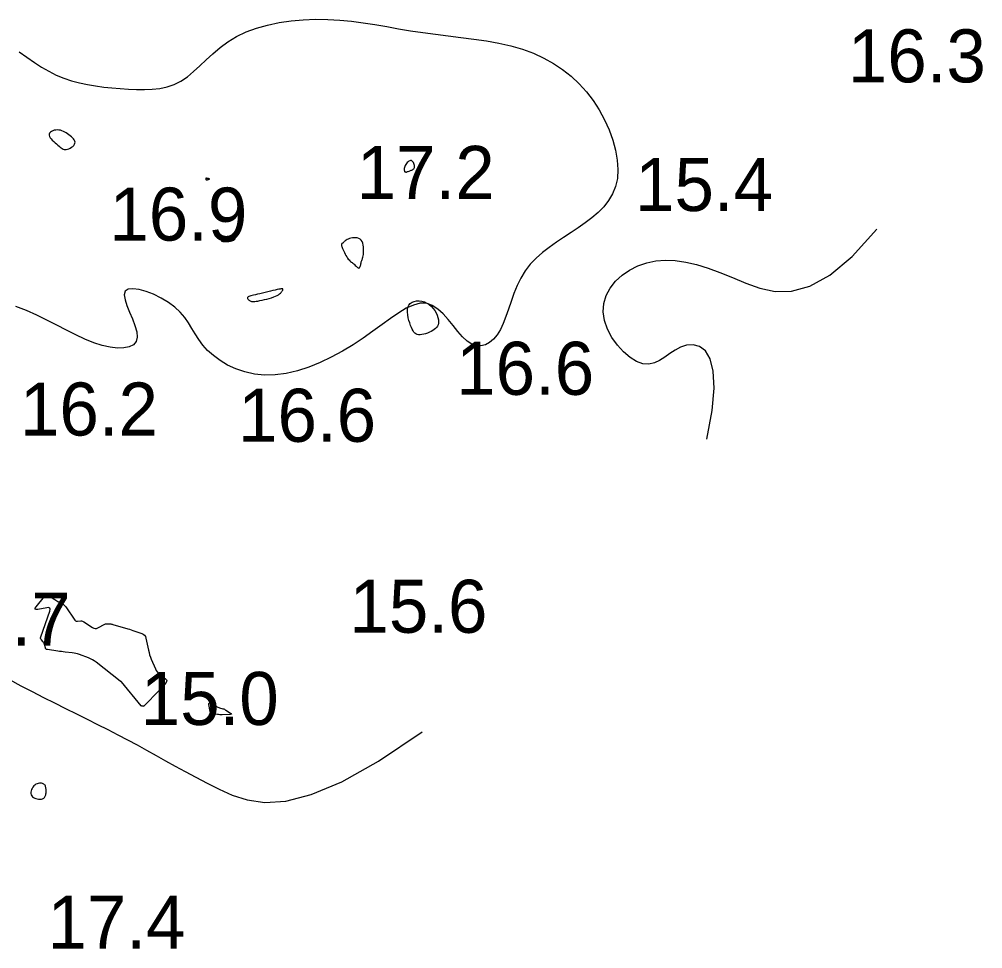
# Model space of a CAD drawing. Extents: x 3040093 to 3056816, y 408076 to 509144.
# Drawn here: x 3045686.7 to 3045777.5, y 433863.6 to 433951.2 of the extents above; entities that cross this region are included whole.
import ezdxf

# ---------------------------------------------------------------- set-up
doc = ezdxf.new("R2010")
doc.units = 0
for name, color, linetype in [('V-CHAN-CONT-EL15', 7, 'Continuous'), ('V-CHAN-CONT-EL17', 7, 'Continuous'), ('V-TOPO-SOUN-0610', 7, 'Continuous')]:
    doc.layers.add(name, color=color, linetype=linetype)

msp = doc.modelspace()

# ---------------------------------------------------------------- linework, layer by layer
at = {"layer": 'V-CHAN-CONT-EL15'}
for points in [[(3045700.137, 433888.23), (3045700.06, 433888.141), (3045699.981, 433888.054), (3045699.9, 433887.97), (3045698.417, 433886.459), (3045698.401, 433886.446), (3045698.384, 433886.438), (3045698.365, 433886.435), (3045698.345, 433886.436), (3045698.225, 433886.457), (3045698.215, 433886.459), (3045698.198, 433886.464), (3045698.192, 433886.466), (3045698.186, 433886.469), (3045698.175, 433886.476), (3045698.17, 433886.479), (3045698.166, 433886.484), (3045696.303, 433888.739), (3045696.295, 433888.748), (3045696.286, 433888.755), (3045696.277, 433888.761), (3045696.266, 433888.765), (3045696.223, 433888.782), (3045696.212, 433888.786), (3045696.202, 433888.792), (3045696.192, 433888.798), (3045696.183, 433888.804), (3045693.903, 433890.589), (3045693.734, 433890.711), (3045693.558, 433890.82), (3045693.374, 433890.916), (3045693.182, 433890.998), (3045692.333, 433891.326), (3045692.171, 433891.383), (3045692.005, 433891.428), (3045691.838, 433891.463), (3045691.667, 433891.486), (3045690.979, 433891.555), (3045690.807, 433891.574), (3045690.635, 433891.594), (3045690.464, 433891.616), (3045690.293, 433891.641), (3045689.315, 433891.786), (3045689.246, 433891.805), (3045689.192, 433891.84), (3045689.152, 433891.89), (3045689.126, 433891.956), (3045689.048, 433892.261), (3045689.027, 433892.329), (3045688.998, 433892.393), (3045688.962, 433892.454), (3045688.92, 433892.51), (3045688.735, 433892.73), (3045688.697, 433892.787), (3045688.677, 433892.847), (3045688.674, 433892.91), (3045688.689, 433892.976), (3045689.533, 433895.411), (3045689.568, 433895.583), (3045689.533, 433895.695), (3045689.428, 433895.746), (3045689.253, 433895.736), (3045688.412, 433895.577), (3045688.245, 433895.563), (3045688.165, 433895.6), (3045688.171, 433895.689), (3045688.264, 433895.828), (3045689.057, 433896.788), (3045689.152, 433896.875), (3045689.255, 433896.915), (3045689.364, 433896.908), (3045689.481, 433896.853), (3045690.032, 433896.496), (3045690.119, 433896.44), (3045690.207, 433896.386), (3045690.296, 433896.334), (3045690.386, 433896.283), (3045690.747, 433896.083), (3045690.833, 433896.028), (3045690.912, 433895.965), (3045690.983, 433895.893), (3045691.045, 433895.813), (3045691.912, 433894.567), (3045691.961, 433894.512), (3045692.018, 433894.475), (3045692.083, 433894.456), (3045692.156, 433894.454), (3045692.466, 433894.485), (3045692.542, 433894.486), (3045692.614, 433894.474), (3045692.683, 433894.45), (3045692.749, 433894.412), (3045693.56, 433893.855), (3045693.682, 433893.791), (3045693.807, 433893.765), (3045693.933, 433893.776), (3045694.062, 433893.826), (3045694.726, 433894.174), (3045694.785, 433894.2), (3045694.846, 433894.218), (3045694.909, 433894.227), (3045694.973, 433894.227), (3045695.235, 433894.211), (3045695.3, 433894.205), (3045695.365, 433894.196), (3045695.429, 433894.183), (3045695.492, 433894.166), (3045696.891, 433893.751), (3045697.058, 433893.7), (3045697.224, 433893.647), (3045697.39, 433893.593), (3045697.555, 433893.536), (3045698.213, 433893.306), (3045698.362, 433893.234), (3045698.478, 433893.134), (3045698.562, 433893.006), (3045698.614, 433892.849), (3045698.849, 433891.717), (3045698.9, 433891.503), (3045698.96, 433891.292), (3045699.031, 433891.085), (3045699.113, 433890.881), (3045699.507, 433889.964), (3045699.579, 433889.822), (3045699.666, 433889.692), (3045699.77, 433889.574), (3045699.889, 433889.468), (3045700.468, 433889.015), (3045700.54, 433888.941), (3045700.57, 433888.861), (3045700.559, 433888.776), (3045700.506, 433888.687), (3045700.212, 433888.321)], [(3045705.943, 433886.185), (3045706.017, 433886.154), (3045706.088, 433886.118), (3045706.157, 433886.077), (3045706.59, 433885.801), (3045706.658, 433885.747), (3045706.675, 433885.708), (3045706.641, 433885.683), (3045706.554, 433885.672), (3045705.798, 433885.647), (3045705.687, 433885.645), (3045705.576, 433885.646), (3045705.465, 433885.652), (3045705.355, 433885.661), (3045704.913, 433885.703), (3045704.814, 433885.726), (3045704.739, 433885.774), (3045704.686, 433885.847), (3045704.656, 433885.944), (3045704.548, 433886.607), (3045704.543, 433886.711), (3045704.572, 433886.766), (3045704.635, 433886.774), (3045704.73, 433886.734), (3045705.263, 433886.43), (3045705.334, 433886.392), (3045705.407, 433886.358), (3045705.482, 433886.329), (3045705.558, 433886.304), (3045705.867, 433886.211)]]:
    msp.add_lwpolyline(points, close=True, dxfattribs=at)
at = {"layer": 'V-CHAN-CONT-EL17'}
for points in [[(3045686.664, 433948.139), (3045687.389, 433947.637), (3045688.089, 433947.16), (3045688.774, 433946.718), (3045689.456, 433946.316), (3045690.149, 433945.965), (3045690.861, 433945.669), (3045691.591, 433945.424), (3045692.337, 433945.224), (3045693.095, 433945.063), (3045693.862, 433944.935), (3045694.634, 433944.833), (3045695.408, 433944.752), (3045696.182, 433944.686), (3045696.951, 433944.629), (3045697.713, 433944.593), (3045698.463, 433944.586), (3045699.198, 433944.621), (3045699.914, 433944.709), (3045700.608, 433944.86), (3045701.275, 433945.086), (3045701.912, 433945.399), (3045702.518, 433945.804), (3045703.107, 433946.285), (3045703.694, 433946.821), (3045704.295, 433947.391), (3045704.925, 433947.975), (3045705.6, 433948.55), (3045706.337, 433949.097), (3045707.151, 433949.594), (3045708.053, 433950.023), (3045709.034, 433950.384), (3045710.078, 433950.677), (3045711.172, 433950.906), (3045712.302, 433951.071), (3045713.452, 433951.176), (3045714.609, 433951.221), (3045715.758, 433951.21), (3045716.889, 433951.144), (3045718.003, 433951.034), (3045719.109, 433950.887), (3045720.212, 433950.715), (3045721.318, 433950.527), (3045722.435, 433950.333), (3045723.569, 433950.142), (3045724.726, 433949.964), (3045725.91, 433949.805), (3045727.114, 433949.658), (3045728.325, 433949.511), (3045729.534, 433949.354), (3045730.729, 433949.174), (3045731.899, 433948.961), (3045733.035, 433948.703), (3045734.123, 433948.39), (3045735.157, 433948.011), (3045736.132, 433947.566), (3045737.051, 433947.056), (3045737.912, 433946.481), (3045738.716, 433945.842), (3045739.462, 433945.14), (3045740.15, 433944.377), (3045740.781, 433943.552), (3045741.353, 433942.669), (3045741.859, 433941.743), (3045742.291, 433940.79), (3045742.642, 433939.828), (3045742.904, 433938.873), (3045743.069, 433937.942), (3045743.129, 433937.052), (3045743.076, 433936.221), (3045742.905, 433935.46), (3045742.627, 433934.767), (3045742.252, 433934.132), (3045741.795, 433933.547), (3045741.267, 433933.006), (3045740.681, 433932.498), (3045740.05, 433932.017), (3045739.386, 433931.554), (3045738.701, 433931.101), (3045738.008, 433930.649), (3045737.319, 433930.191), (3045736.647, 433929.716), (3045736.003, 433929.218), (3045735.401, 433928.687), (3045734.852, 433928.115), (3045734.369, 433927.493), (3045733.959, 433926.818), (3045733.612, 433926.102), (3045733.315, 433925.364), (3045733.051, 433924.621), (3045732.807, 433923.891), (3045732.567, 433923.192), (3045732.318, 433922.542), (3045732.044, 433921.959), (3045731.734, 433921.459), (3045731.391, 433921.049), (3045731.018, 433920.737), (3045730.622, 433920.53), (3045730.208, 433920.433), (3045729.78, 433920.454), (3045729.345, 433920.599), (3045728.906, 433920.875), (3045728.468, 433921.279), (3045728.028, 433921.779), (3045727.581, 433922.333), (3045727.121, 433922.898), (3045726.644, 433923.433), (3045726.146, 433923.896), (3045725.62, 433924.245), (3045725.063, 433924.437), (3045724.471, 433924.444), (3045723.839, 433924.278), (3045723.167, 433923.968), (3045722.451, 433923.538), (3045721.69, 433923.016), (3045720.88, 433922.428), (3045720.021, 433921.799), (3045719.109, 433921.157), (3045718.144, 433920.526), (3045717.136, 433919.922), (3045716.095, 433919.359), (3045715.033, 433918.853), (3045713.961, 433918.417), (3045712.891, 433918.067), (3045711.833, 433917.816), (3045710.8, 433917.679), (3045709.8, 433917.667), (3045708.844, 433917.769), (3045707.938, 433917.971), (3045707.09, 433918.26), (3045706.307, 433918.621), (3045705.598, 433919.04), (3045704.97, 433919.503), (3045704.43, 433919.995), (3045703.981, 433920.505), (3045703.602, 433921.026), (3045703.267, 433921.551), (3045702.949, 433922.077), (3045702.624, 433922.599), (3045702.264, 433923.11), (3045701.844, 433923.606), (3045701.337, 433924.081), (3045700.728, 433924.53), (3045700.047, 433924.936), (3045699.332, 433925.285), (3045698.625, 433925.558), (3045697.964, 433925.74), (3045697.39, 433925.815), (3045696.942, 433925.765), (3045696.66, 433925.575), (3045696.569, 433925.236), (3045696.639, 433924.773), (3045696.821, 433924.22), (3045697.069, 433923.608), (3045697.337, 433922.973), (3045697.579, 433922.345), (3045697.747, 433921.759), (3045697.795, 433921.248), (3045697.687, 433920.839), (3045697.429, 433920.534), (3045697.039, 433920.331), (3045696.534, 433920.226), (3045695.93, 433920.216), (3045695.244, 433920.297), (3045694.493, 433920.468), (3045693.695, 433920.724), (3045692.863, 433921.06), (3045692.002, 433921.459), (3045691.114, 433921.903), (3045690.202, 433922.372), (3045689.266, 433922.848), (3045688.31, 433923.312), (3045687.335, 433923.745), (3045686.343, 433924.127)], [(3045751.498, 433911.616), (3045752.009, 433914.327), (3045752.199, 433916.451), (3045752.122, 433918.051), (3045751.831, 433919.194), (3045751.38, 433919.943), (3045750.823, 433920.363), (3045750.213, 433920.52), (3045749.604, 433920.478), (3045749.039, 433920.297), (3045748.515, 433920.022), (3045748.019, 433919.696), (3045747.538, 433919.359), (3045747.058, 433919.053), (3045746.565, 433918.819), (3045746.048, 433918.698), (3045745.491, 433918.732), (3045744.89, 433918.95), (3045744.266, 433919.335), (3045743.651, 433919.862), (3045743.073, 433920.5), (3045742.564, 433921.224), (3045742.154, 433922.004), (3045741.871, 433922.815), (3045741.747, 433923.626), (3045741.804, 433924.415), (3045742.03, 433925.166), (3045742.405, 433925.868), (3045742.91, 433926.511), (3045743.525, 433927.082), (3045744.231, 433927.571), (3045745.008, 433927.966), (3045745.837, 433928.257), (3045746.701, 433928.434), (3045747.601, 433928.5), (3045748.539, 433928.461), (3045749.52, 433928.322), (3045750.547, 433928.088), (3045751.622, 433927.765), (3045752.75, 433927.359), (3045753.934, 433926.874), (3045755.18, 433926.336), (3045756.51, 433925.856), (3045757.945, 433925.562), (3045759.51, 433925.585), (3045761.228, 433926.053), (3045763.123, 433927.098), (3045765.218, 433928.848), (3045767.536, 433931.434)], [(3045685.728, 433888.957), (3045686.812, 433888.381), (3045687.887, 433887.823), (3045688.95, 433887.28), (3045690.001, 433886.751), (3045691.035, 433886.234), (3045692.053, 433885.727), (3045693.054, 433885.229), (3045694.037, 433884.737), (3045695.002, 433884.249), (3045695.949, 433883.764), (3045696.877, 433883.28), (3045697.785, 433882.794), (3045698.677, 433882.305), (3045699.562, 433881.81), (3045700.454, 433881.309), (3045701.368, 433880.798), (3045702.317, 433880.277), (3045703.315, 433879.742), (3045704.374, 433879.193), (3045705.51, 433878.628), (3045706.747, 433878.064), (3045708.154, 433877.607), (3045709.812, 433877.379), (3045711.8, 433877.506), (3045714.2, 433878.11), (3045717.092, 433879.317), (3045720.556, 433881.251), (3045724.673, 433884.036)]]:
    msp.add_lwpolyline(points, dxfattribs=at)
for points in [[(3045691.217, 433938.96), (3045691.344, 433939.006), (3045691.472, 433939.069), (3045691.595, 433939.146), (3045691.707, 433939.233), (3045691.802, 433939.329), (3045691.874, 433939.43), (3045691.917, 433939.533), (3045691.927, 433939.637), (3045691.906, 433939.741), (3045691.857, 433939.844), (3045691.785, 433939.946), (3045691.695, 433940.046), (3045691.589, 433940.144), (3045691.472, 433940.24), (3045691.349, 433940.333), (3045691.221, 433940.423), (3045691.091, 433940.507), (3045690.958, 433940.585), (3045690.823, 433940.653), (3045690.684, 433940.709), (3045690.543, 433940.752), (3045690.399, 433940.779), (3045690.253, 433940.788), (3045690.105, 433940.778), (3045689.96, 433940.749), (3045689.824, 433940.704), (3045689.702, 433940.644), (3045689.6, 433940.57), (3045689.523, 433940.484), (3045689.478, 433940.388), (3045689.47, 433940.284), (3045689.502, 433940.172), (3045689.569, 433940.056), (3045689.664, 433939.936), (3045689.781, 433939.815), (3045689.911, 433939.695), (3045690.047, 433939.577), (3045690.182, 433939.463), (3045690.31, 433939.356), (3045690.424, 433939.257), (3045690.527, 433939.167), (3045690.621, 433939.089), (3045690.711, 433939.024), (3045690.8, 433938.975), (3045690.892, 433938.942), (3045690.99, 433938.927), (3045691.097, 433938.933)], [(3045723.08, 433936.821), (3045723.125, 433936.814), (3045723.175, 433936.819), (3045723.231, 433936.833), (3045723.292, 433936.854), (3045723.356, 433936.879), (3045723.423, 433936.906), (3045723.493, 433936.933), (3045723.564, 433936.958), (3045723.635, 433936.981), (3045723.703, 433937.007), (3045723.766, 433937.036), (3045723.823, 433937.073), (3045723.87, 433937.118), (3045723.906, 433937.174), (3045723.928, 433937.244), (3045723.936, 433937.329), (3045723.929, 433937.424), (3045723.908, 433937.523), (3045723.876, 433937.622), (3045723.832, 433937.714), (3045723.779, 433937.793), (3045723.717, 433937.853), (3045723.648, 433937.89), (3045723.572, 433937.899), (3045723.493, 433937.881), (3045723.412, 433937.841), (3045723.331, 433937.783), (3045723.254, 433937.709), (3045723.183, 433937.625), (3045723.119, 433937.533), (3045723.066, 433937.437), (3045723.026, 433937.34), (3045722.997, 433937.246), (3045722.98, 433937.156), (3045722.973, 433937.072), (3045722.977, 433936.997), (3045722.99, 433936.932), (3045723.012, 433936.88), (3045723.042, 433936.843)], [(3045704.406, 433936.094), (3045704.442, 433936.102), (3045704.479, 433936.111), (3045704.516, 433936.121), (3045704.548, 433936.132), (3045704.576, 433936.143), (3045704.596, 433936.153), (3045704.607, 433936.162), (3045704.607, 433936.17), (3045704.597, 433936.176), (3045704.579, 433936.182), (3045704.555, 433936.187), (3045704.527, 433936.191), (3045704.496, 433936.194), (3045704.466, 433936.198), (3045704.437, 433936.202), (3045704.411, 433936.206), (3045704.389, 433936.211), (3045704.369, 433936.215), (3045704.352, 433936.219), (3045704.336, 433936.223), (3045704.323, 433936.227), (3045704.312, 433936.23), (3045704.301, 433936.231), (3045704.292, 433936.232), (3045704.283, 433936.231), (3045704.276, 433936.23), (3045704.269, 433936.227), (3045704.263, 433936.223), (3045704.258, 433936.217), (3045704.253, 433936.211), (3045704.25, 433936.203), (3045704.247, 433936.194), (3045704.246, 433936.183), (3045704.245, 433936.172), (3045704.245, 433936.161), (3045704.246, 433936.15), (3045704.248, 433936.138), (3045704.251, 433936.127), (3045704.255, 433936.117), (3045704.26, 433936.108), (3045704.267, 433936.1), (3045704.277, 433936.094), (3045704.289, 433936.089), (3045704.304, 433936.085), (3045704.322, 433936.084), (3045704.346, 433936.085), (3045704.373, 433936.088)], [(3045706.817, 433930.36), (3045706.905, 433930.405), (3045706.971, 433930.454), (3045707.016, 433930.506), (3045707.042, 433930.559), (3045707.048, 433930.609), (3045707.037, 433930.656), (3045707.009, 433930.697), (3045706.964, 433930.729), (3045706.905, 433930.753), (3045706.832, 433930.768), (3045706.747, 433930.775), (3045706.652, 433930.773), (3045706.547, 433930.762), (3045706.435, 433930.742), (3045706.316, 433930.713), (3045706.194, 433930.674), (3045706.072, 433930.629), (3045705.958, 433930.58), (3045705.857, 433930.527), (3045705.777, 433930.474), (3045705.722, 433930.423), (3045705.699, 433930.376), (3045705.714, 433930.336), (3045705.772, 433930.304), (3045705.865, 433930.28), (3045705.986, 433930.265), (3045706.126, 433930.258), (3045706.277, 433930.261), (3045706.429, 433930.272), (3045706.576, 433930.292), (3045706.707, 433930.322)], [(3045718.763, 433927.795), (3045718.795, 433927.844), (3045718.822, 433927.909), (3045718.844, 433927.988), (3045718.864, 433928.075), (3045718.883, 433928.165), (3045718.902, 433928.255), (3045718.922, 433928.339), (3045718.945, 433928.414), (3045718.97, 433928.485), (3045718.997, 433928.554), (3045719.023, 433928.627), (3045719.049, 433928.708), (3045719.074, 433928.801), (3045719.097, 433928.912), (3045719.117, 433929.044), (3045719.132, 433929.2), (3045719.141, 433929.375), (3045719.141, 433929.561), (3045719.129, 433929.75), (3045719.104, 433929.936), (3045719.061, 433930.111), (3045718.999, 433930.267), (3045718.916, 433930.396), (3045718.809, 433930.494), (3045718.683, 433930.561), (3045718.543, 433930.602), (3045718.394, 433930.62), (3045718.241, 433930.618), (3045718.09, 433930.601), (3045717.946, 433930.572), (3045717.814, 433930.534), (3045717.697, 433930.491), (3045717.597, 433930.444), (3045717.51, 433930.395), (3045717.436, 433930.346), (3045717.372, 433930.297), (3045717.319, 433930.251), (3045717.273, 433930.21), (3045717.234, 433930.173), (3045717.2, 433930.144), (3045717.17, 433930.12), (3045717.145, 433930.101), (3045717.124, 433930.086), (3045717.105, 433930.074), (3045717.09, 433930.064), (3045717.077, 433930.054), (3045717.066, 433930.044), (3045717.057, 433930.032), (3045717.05, 433930.016), (3045717.047, 433929.995), (3045717.049, 433929.965), (3045717.056, 433929.924), (3045717.071, 433929.871), (3045717.093, 433929.802), (3045717.124, 433929.716), (3045717.165, 433929.611), (3045717.214, 433929.49), (3045717.271, 433929.36), (3045717.334, 433929.223), (3045717.401, 433929.085), (3045717.473, 433928.95), (3045717.546, 433928.823), (3045717.62, 433928.709), (3045717.694, 433928.61), (3045717.767, 433928.526), (3045717.841, 433928.453), (3045717.914, 433928.388), (3045717.988, 433928.328), (3045718.061, 433928.271), (3045718.135, 433928.212), (3045718.209, 433928.15), (3045718.283, 433928.083), (3045718.357, 433928.012), (3045718.429, 433927.944), (3045718.498, 433927.881), (3045718.563, 433927.828), (3045718.623, 433927.788), (3045718.677, 433927.767), (3045718.724, 433927.769)], [(3045709.367, 433924.688), (3045709.574, 433924.732), (3045709.794, 433924.782), (3045710.019, 433924.84), (3045710.243, 433924.902), (3045710.458, 433924.969), (3045710.658, 433925.038), (3045710.836, 433925.109), (3045710.986, 433925.181), (3045711.109, 433925.252), (3045711.21, 433925.321), (3045711.289, 433925.388), (3045711.352, 433925.452), (3045711.4, 433925.512), (3045711.437, 433925.566), (3045711.466, 433925.614), (3045711.49, 433925.654), (3045711.508, 433925.689), (3045711.522, 433925.717), (3045711.531, 433925.741), (3045711.536, 433925.76), (3045711.536, 433925.775), (3045711.533, 433925.787), (3045711.526, 433925.797), (3045711.514, 433925.805), (3045711.494, 433925.811), (3045711.463, 433925.813), (3045711.416, 433925.81), (3045711.348, 433925.801), (3045711.257, 433925.786), (3045711.138, 433925.762), (3045710.986, 433925.73), (3045710.8, 433925.687), (3045710.585, 433925.637), (3045710.35, 433925.582), (3045710.102, 433925.523), (3045709.849, 433925.462), (3045709.599, 433925.402), (3045709.359, 433925.346), (3045709.138, 433925.294), (3045708.942, 433925.25), (3045708.771, 433925.211), (3045708.625, 433925.177), (3045708.502, 433925.145), (3045708.4, 433925.115), (3045708.32, 433925.085), (3045708.26, 433925.054), (3045708.219, 433925.019), (3045708.196, 433924.981), (3045708.189, 433924.939), (3045708.196, 433924.895), (3045708.216, 433924.851), (3045708.247, 433924.807), (3045708.286, 433924.764), (3045708.333, 433924.725), (3045708.385, 433924.69), (3045708.442, 433924.66), (3045708.505, 433924.637), (3045708.577, 433924.62), (3045708.662, 433924.61), (3045708.761, 433924.608), (3045708.879, 433924.614), (3045709.018, 433924.629), (3045709.18, 433924.654)], [(3045723.491, 433922.583), (3045723.416, 433922.827), (3045723.35, 433923.083), (3045723.301, 433923.342), (3045723.275, 433923.597), (3045723.279, 433923.839), (3045723.32, 433924.061), (3045723.403, 433924.253), (3045723.534, 433924.41), (3045723.706, 433924.531), (3045723.91, 433924.614), (3045724.138, 433924.66), (3045724.381, 433924.668), (3045724.63, 433924.639), (3045724.876, 433924.572), (3045725.112, 433924.467), (3045725.328, 433924.326), (3045725.524, 433924.154), (3045725.697, 433923.958), (3045725.848, 433923.747), (3045725.974, 433923.528), (3045726.074, 433923.307), (3045726.148, 433923.093), (3045726.195, 433922.893), (3045726.213, 433922.713), (3045726.204, 433922.552), (3045726.17, 433922.408), (3045726.111, 433922.279), (3045726.03, 433922.162), (3045725.927, 433922.056), (3045725.805, 433921.959), (3045725.665, 433921.868), (3045725.509, 433921.782), (3045725.341, 433921.702), (3045725.164, 433921.631), (3045724.985, 433921.571), (3045724.807, 433921.523), (3045724.634, 433921.491), (3045724.471, 433921.476), (3045724.323, 433921.48), (3045724.192, 433921.506), (3045724.077, 433921.555), (3045723.976, 433921.626), (3045723.885, 433921.722), (3045723.802, 433921.842), (3045723.723, 433921.988), (3045723.647, 433922.159), (3045723.57, 433922.358)], [(3045688.687, 433877.669), (3045688.775, 433877.682), (3045688.853, 433877.705), (3045688.92, 433877.738), (3045688.979, 433877.78), (3045689.029, 433877.83), (3045689.072, 433877.888), (3045689.107, 433877.953), (3045689.135, 433878.024), (3045689.158, 433878.1), (3045689.175, 433878.181), (3045689.187, 433878.265), (3045689.194, 433878.35), (3045689.197, 433878.437), (3045689.195, 433878.524), (3045689.19, 433878.61), (3045689.182, 433878.694), (3045689.169, 433878.775), (3045689.151, 433878.852), (3045689.125, 433878.924), (3045689.092, 433878.99), (3045689.049, 433879.048), (3045688.995, 433879.099), (3045688.929, 433879.141), (3045688.85, 433879.172), (3045688.761, 433879.193), (3045688.664, 433879.201), (3045688.56, 433879.195), (3045688.454, 433879.175), (3045688.346, 433879.139), (3045688.24, 433879.086), (3045688.139, 433879.014), (3045688.044, 433878.924), (3045687.958, 433878.819), (3045687.884, 433878.703), (3045687.825, 433878.579), (3045687.784, 433878.453), (3045687.763, 433878.327), (3045687.764, 433878.207), (3045687.791, 433878.096), (3045687.844, 433877.998), (3045687.921, 433877.913), (3045688.016, 433877.841), (3045688.124, 433877.781), (3045688.24, 433877.735), (3045688.359, 433877.7), (3045688.477, 433877.678), (3045688.587, 433877.668)]]:
    msp.add_lwpolyline(points, close=True, dxfattribs=at)

# ---------------------------------------------------------------- texts
at = {"layer": 'V-TOPO-SOUN-0610'}
for s, p in [('16.3 ', (3045764.813, 433945.27)), ('17.2 ', (3045718.493, 433934.28)), ('15.4 ', (3045744.743, 433933.14)), ('16.9 ', (3045695.163, 433930.35)), ('16.6 ', (3045727.873, 433915.81)), ('16.2 ', (3045686.733, 433911.97)), ('16.6 ', (3045707.303, 433911.38)), ('15.6 ', (3045717.803, 433893.37)), ('14.7 ', (3045678.503, 433892.16)), ('15.0 ', (3045698.123, 433884.68)), ('17.4 ', (3045689.323, 433863.58))]:
    msp.add_text(s, height=5, dxfattribs=at).set_placement(p)

doc.saveas('drawing.dxf')
